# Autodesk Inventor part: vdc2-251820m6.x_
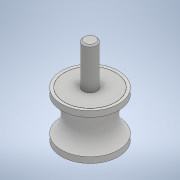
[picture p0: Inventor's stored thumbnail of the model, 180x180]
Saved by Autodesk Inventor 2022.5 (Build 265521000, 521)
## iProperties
Created: 2018-04
Part Number: vdc2-251820m6.x_
Material: 一般
Document SubType Name: Modeling
Designer: imaocorp
Density: 1 g/cm^3
Appearance: 既定
Sending System: SOLIDWORKS 2016-2016286
MC: AMD64
MC_MODEL: AMD64 Family 21 Model 2 Stepping 0, AuthenticAMD
OS: Windows_NT
FRU: Parasolid Version 28.0, build 224,  7-29-2016
FORMAT: text
GUISE: transmit
KEY: vdc2-251820m6
FILE: vdc2-251820m6.x_t
DATE: Wed Apr 25 10:15:09 2018
Author: imaocorp
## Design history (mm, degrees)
feature "Base1"
node "ソリッド1"
